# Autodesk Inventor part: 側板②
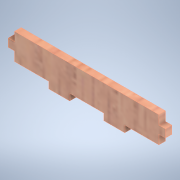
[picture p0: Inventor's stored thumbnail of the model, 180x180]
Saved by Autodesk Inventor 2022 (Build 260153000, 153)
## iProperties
Created: 2024-11
Part Number: 側板②
Material: 木 (オーク)
Document SubType Name: Modeling
Designer: shimizu
Density: 0.76 g/cm^3
Appearance: ホワイト オーク材 - ナチュラル 標準の光沢
Author: shimizu
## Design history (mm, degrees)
sketch "スケッチ1"
  geometry: L1 (-25.358, 1.343)-(29.642, 1.343); L2 (-4.358, -8.657)-(-4.358, -11.157); L3 (-4.358, -11.157)-(-12.358, -11.157); L4 (-12.358, -11.157)-(-12.358, -8.657); L5 (16.642, -8.657)-(16.642, -11.157); L6 (16.642, -11.157)-(8.642, -11.157); L7 (8.642, -11.157)-(8.642, -8.657); L8 (-25.358, -2.157)-(-27.858, -2.157); L9 (-27.858, -2.157)-(-27.858, -5.157); L10 (-27.858, -5.157)-(-25.358, -5.157); L11 (29.642, -2.157)-(32.142, -2.157); L12 (32.142, -2.157)-(32.142, -5.157); L13 (32.142, -5.157)-(29.642, -5.157); L14 (-25.358, -8.657)-(-25.358, -5.157); L15 (-25.358, -2.157)-(-25.358, 1.343); L16 (29.642, 1.343)-(29.642, -2.157); L17 (29.642, -5.157)-(29.642, -8.657); L18 (29.642, -8.657)-(16.642, -8.657); L19 (8.642, -8.657)-(-4.358, -8.657); L20 (-12.358, -8.657)-(-25.358, -8.657); 1 further point
  constraints: 40 end point, 11 parallel, 4 perpendicular, 3 horizontal
  dimensions: "d16" = 13 distance of L17.end L5.start; "d17" = 13 distance of L4.end L14.start; "d18" = 8 distance of L5.end L6.end; "d19" = 8 distance of L2.end L3.end; "d20" = 13 distance of L7.end L2.start; "d21" = 55 distance between parallel lines of L16 L15; "d22" = 60 distance between parallel lines of L12 L9; "d23" = 3.5 distance between parallel lines of L8 L1; "d24" = 3.5 distance between parallel lines of L20 L10; "d25" = 3.5 distance between parallel lines of L11 L1; "d26" = 3.5 distance between parallel lines of L18 L13; "d27" = 3 distance of L8.end L9.end; "d28" = 3 distance of L11.end L12.end
extrude "押し出し1" new body sketch "スケッチ1" distance "d14" = 2.5; taper "d15" = 0 deg
node "ソリッド1"
